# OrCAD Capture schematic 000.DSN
size C
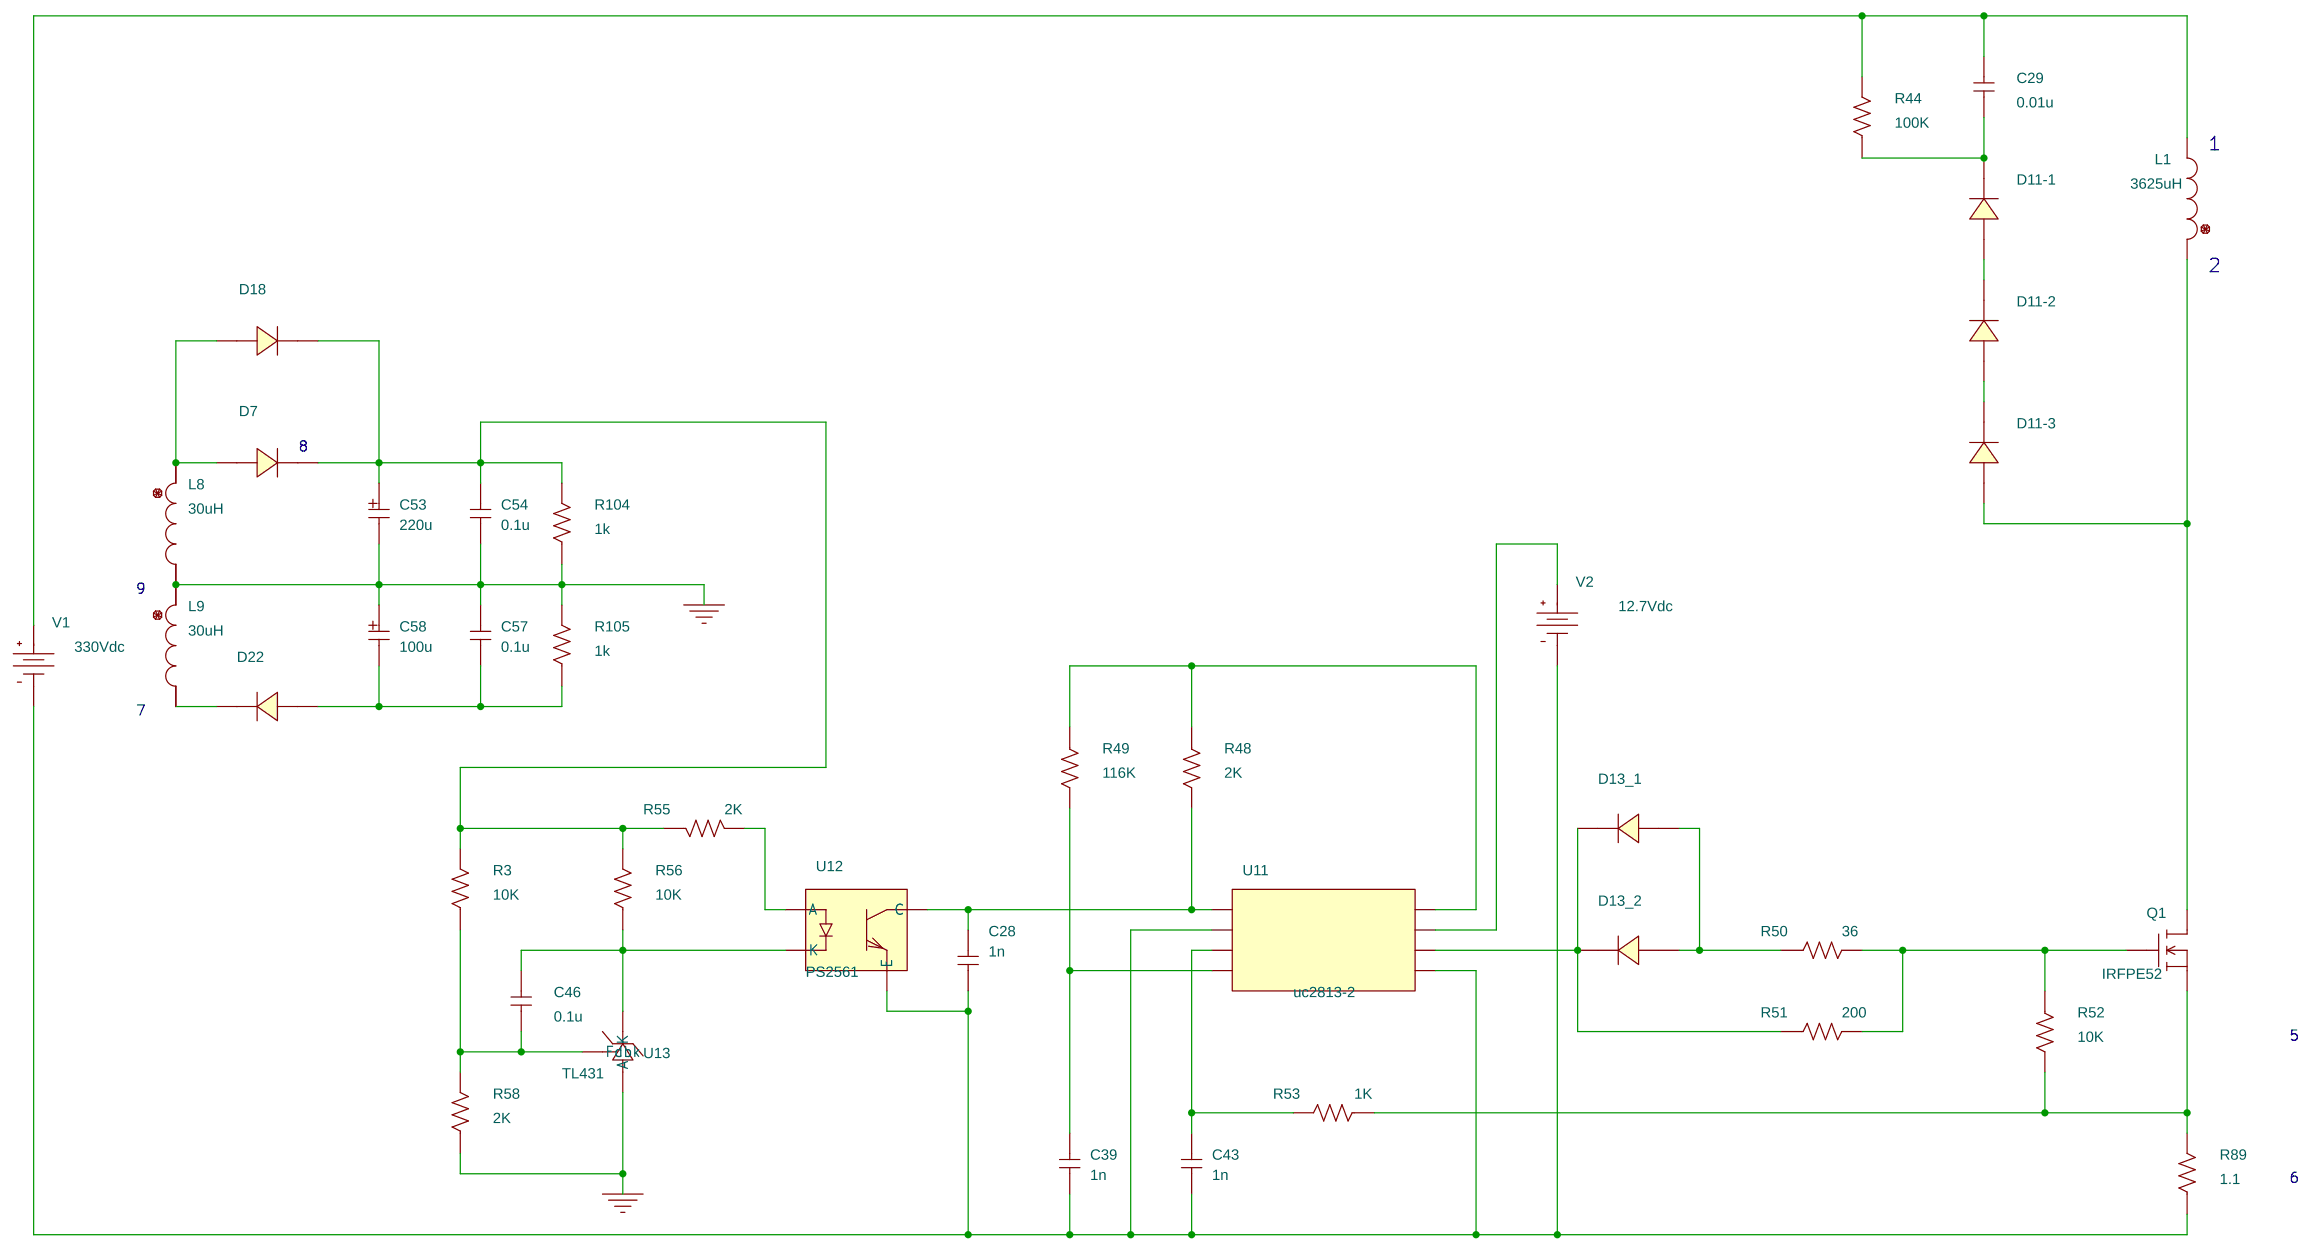
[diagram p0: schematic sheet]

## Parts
C28  1n  [RAD/CK05]
C29  0.01u  [RAD/CK05]
C39  1n  [RAD/CK05]
C43  1n  [RAD/CK05]
C46  0.1u  [RAD/CK05]
C53  220u  [CPAX/.575x.150/.031]
C54  0.1u  [RAD/CK05]
C57  0.1u  [RAD/CK05]
C58  100u  [CPAX/.575x.150/.031]
D7  DMURS160T3
D11-1  DMURS160T3
D11-2  DMURS160T3
D11-3  DMURS160T3
D13_1  DBAW56LT1
D13_2  DBAW56LT1
D18  DMURS160T3
D22  DMURS160T3
L1  3625uH  [DISC/.350x.175/LS.200x.100/.034]
L8  30uH  [DISC/.350x.175/LS.200x.100/.034]
L9  30uH  [DISC/.350x.175/LS.200x.100/.034]
Q1  IRFPE52  [TO247AC]
R3  10K  [AX/RC05]
R44  100K  [AX/RC05]
R48  2K  [AX/RC05]
R49  116K  [AX/RC05]
R50  36  [AX/RC05]
R51  200  [AX/RC05]
R52  10K  [AX/RC05]
R53  1K  [AX/RC05]
R55  2K  [AX/RC05]
R56  10K  [AX/RC05]
R58  2K  [AX/RC05]
R89  1.1  [AX/RC05]
R104  1k  [AX/RC05]
R105  1k  [AX/RC05]
U11  uc2813-2
U12  PS2561  [DIP4]
U13  TL431
V1  VDC
V2  VDC

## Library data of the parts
C28 C29 C39 C43 C46 C54 C57 = C
C53 C58 = C_elect
D7 D11-1-D11-3 D18 D22 = DMURS160T3
D13_1 D13_2 = DBAW56LT1
L1 L8 L9 = L
Q1 = IRFPE52
R3 R44 R48-R53 R55 R56 R58 R89 R104 R105 = R
U11 = UCCx813-2_UCCx802
U12 = PS2561-1
U13 = TL431
V1 = VDC: DC: 330Vdc
V2 = VDC: DC: 12.7Vdc

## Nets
0: C53.N(-) C54.1 C57.2 C58.P(+) L8.2 L9.1 R58.1 R104.1 R105.2 U13.A
N16686882: D13_1.2(A) D13_2.2(A) R50.1
N16686956: C46.1 R56.1 U12.2(K) U13.K
N16686960: C46.2 R3.1 R58.2 U13.Fdbk
N16686968: C28.2 R48.2 U11.COMP U12.4(C)
N16686974: R55.2 U12.1(A)
N16687010: D13_1.1(C) D13_2.1(C) R51.1 U11.OUT
N16687014: C29.2 L1.2 R44.2 V1.0(+)
N16687034: Q1.3(S) R52.2 R53.1 R89.2
N16687064: Q1.1(G) R50.2 R51.2 R52.1
N16687068: C29.1 D11-1.1(C) R44.1
N16687168: C28.1 C39.1 C43.2 R89.1 U11.FB U11.GND U12.3(E) V1.1(-) V2.1(-)
N16687176: C39.2 R49.2 U11.RC
N16687184: R48.1 R49.1 U11.VREF
N16687222: U11.VCC V2.0(+)
N16687420: C43.1 R53.2 U11.CS
N16687662: D11-3.2(A) L1.1 Q1.2(D)
N16687708: C53.P(+) C54.2 D7.1(C) D18.1(C) R3.2 R55.1 R56.2 R104.2
N16688348: D7.2(A) D18.2(A) L8.1
N16688352: C57.1 C58.N(-) D22.2(A) R105.1
N16688460: D22.1(C) L9.2
N16689040: D11-1.2(A) D11-2.1(C)
N16689050: D11-2.2(A) D11-3.1(C)

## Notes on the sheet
- 1
- 2
- 8
- 9
- 7
- 5
- 6
